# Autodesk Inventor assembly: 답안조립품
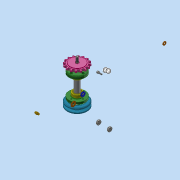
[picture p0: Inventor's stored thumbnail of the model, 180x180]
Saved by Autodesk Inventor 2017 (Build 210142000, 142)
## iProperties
Part Number: 답안조립품
Material: 일반
Document SubType Name: Assembly
Designer: user
Author: user
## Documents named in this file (16)
- C:\Users\user\Desktop\711206V1014\답안조립품.iam
- C:\Users\user\Desktop\711206V1014\V벨트풀리.ipt
- C:\Users\user\Desktop\711206V1014\너트 M8.ipt
- C:\Users\user\Desktop\711206V1014\니플 M6 x 0.75.ipt
- C:\Users\user\Desktop\711206V1014\베어링 6002.ipt
- C:\Users\user\Desktop\711206V1014\본체.ipt
- C:\Users\user\Desktop\711206V1014\볼트 M4 x 12.ipt
- C:\Users\user\Desktop\711206V1014\볼트 M6 x 8.ipt
- C:\Users\user\Desktop\711206V1014\스프로킷.ipt
- C:\Users\user\Desktop\711206V1014\스프링와셔 8.ipt
- C:\Users\user\Desktop\711206V1014\오일 실 15 x 25 x 7.ipt
- C:\Users\user\Desktop\711206V1014\와셔 6 x 11.5.ipt
- C:\Users\user\Desktop\711206V1014\와셔 8 x 17.ipt
- C:\Users\user\Desktop\711206V1014\축.ipt
- C:\Users\user\Desktop\711206V1014\커버.ipt
- C:\Users\user\Desktop\711206V1014\키 3 x 3.ipt
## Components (4 placed, 3 different names)
1. V벨트풀리:1
2. KS B 2023 6002 - 15 x 32 x 9:1
3. ISO 4762 M4 x 12:1
4. KS B 2023 6002 - 15 x 32 x 9:2
